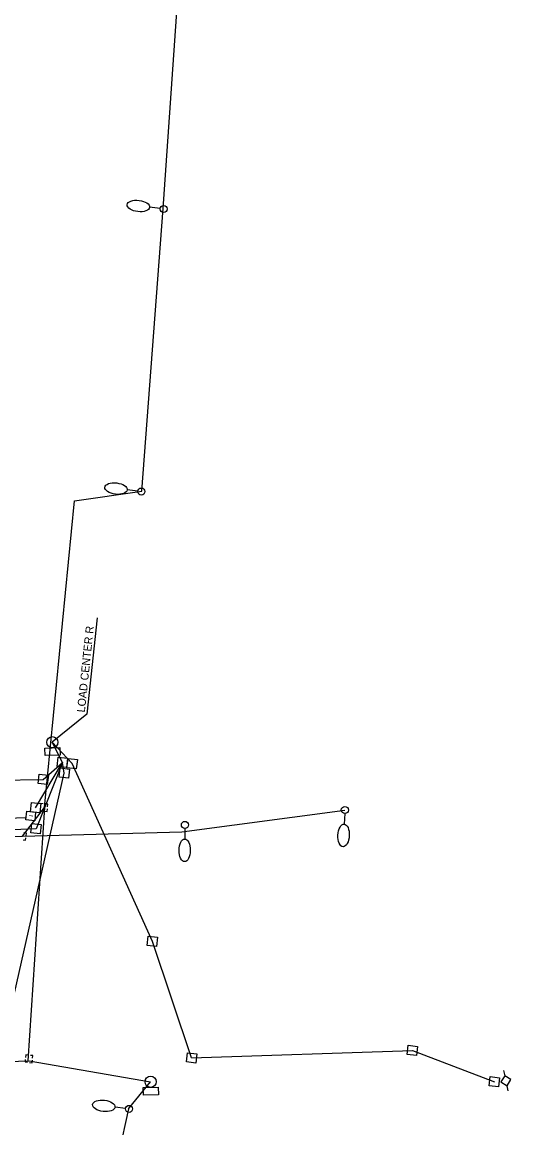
# Model space of a CAD drawing. Extents: x 925407 to 931638, y 609358 to 637063.
# Drawn here: x 931296 to 931638, y 623954 to 624728 of the extents above; entities that cross this region are included whole.
import ezdxf

# ---------------------------------------------------------------- set-up
doc = ezdxf.new("R2010")
doc.units = 0
for name, color, linetype in [('ActivePointCell_dp', 7, 'Continuous'), ('Conduit', 7, 'Continuous'), ('ConduitDB', 7, 'Continuous'), ('ConduitJB', 7, 'Continuous'), ('ConduitOT', 7, 'Continuous'), ('JunctBoxA', 7, 'Continuous'), ('LoadCenter', 7, 'Continuous'), ('LoadCenter_ep', 7, 'Continuous'), ('PoleElec_ep', 7, 'Continuous'), ('PoleLight_ep', 7, 'Continuous'), ('PullBox', 7, 'Continuous')]:
    doc.layers.add(name, color=color, linetype=linetype)

msp = doc.modelspace()

# ---------------------------------------------------------------- linework, layer by layer
at = {"layer": 'ActivePointCell_dp'}
msp.add_line((931348.41, 624311.11), (931341.28, 624243.75), dxfattribs=at)
msp.add_lwpolyline([(931341.28, 624243.75), (931317.05, 624224.02)], dxfattribs=at)
at = {"layer": 'Conduit'}
for p, q in [((931394.8, 624597.39), (931408.64, 624798.05)), ((931379.81, 624399.73), (931394.8, 624597.39)), ((931332.63, 624392.87), (931379.81, 624399.73)), ((931311.62, 624178.47), (931332.63, 624392.87)), ((931296.2, 624158.38), (931311.62, 624178.47)), ((931311.62, 624178.47), (931299.96, 624001.18)), ((931407.77, 624161.41), (931521.93, 624176.6)), ((931086.47, 624152.15), (931296.2, 624158.38)), ((931296.2, 624158.38), (931407.77, 624161.41)), ((931072.34, 623993.5), (931300.82, 624001.21)), ((931300.82, 624001.21), (931385.89, 623986.44)), ((931370.44, 623967.53), (931385.89, 623986.44)), ((931370.44, 623967.53), (931332.04, 623792.24))]:
    msp.add_line(p, q, dxfattribs=at)
at = {"layer": 'ConduitDB'}
for p, q in [((931387.16, 624084.63), (931330.96, 624209.08)), ((931273.51, 623973.41), (931325.4, 624202.39)), ((931213.98, 624196.64), (931310.65, 624198.05)), ((931305.67, 624163.54), (931211.01, 624159.49)), ((931414.61, 624003.2), (931387.16, 624084.63))]:
    msp.add_line(p, q, dxfattribs=at)
msp.add_lwpolyline([(931414.61, 624003.2), (931569.19, 624008.35), (931626.67, 623986.44)], dxfattribs=at)
at = {"layer": 'ConduitJB'}
msp.add_line((931108.8, 624163.39), (931298.74, 624171.44), dxfattribs=at)
at = {"layer": 'ConduitOT'}
for p, q in [((931324.15, 624209.94), (931317.05, 624224.02)), ((931330.96, 624209.08), (931317.05, 624224.02)), ((931305.34, 624178.21), (931324.15, 624209.94)), ((931324.15, 624209.94), (931305.67, 624163.54)), ((931310.65, 624198.05), (931324.15, 624209.94)), ((931325.4, 624202.39), (931324.15, 624209.94))]:
    msp.add_line(p, q, dxfattribs=at)
at = {"layer": 'LoadCenter'}
for p, q in [((931311.93, 624219.97), (931322.38, 624220.24)), ((931312.06, 624214.74), (931311.93, 624219.97)), ((931322.38, 624220.24), (931322.52, 624215.01)), ((931322.52, 624215.01), (931312.06, 624214.74))]:
    msp.add_line(p, q, dxfattribs=at)
msp.add_circle((931317.05, 624224.02), 3.92, dxfattribs=at)
at = {"layer": 'LoadCenter_ep'}
for p, q in [((931380.76, 623982.39), (931391.21, 623982.66)), ((931380.89, 623977.16), (931380.76, 623982.39)), ((931391.35, 623977.43), (931380.89, 623977.16)), ((931391.21, 623982.66), (931391.35, 623977.43))]:
    msp.add_line(p, q, dxfattribs=at)
msp.add_circle((931385.89, 623986.44), 3.92, dxfattribs=at)
at = {"layer": 'PoleElec_ep'}
for p, q in [((931633, 623994.27), (931633.85, 623990.73)), ((931636.41, 623980.17), (931635.56, 623983.71))]:
    msp.add_line(p, q, dxfattribs=at)
msp.add_lwpolyline([(931633.85, 623990.73), (931631.19, 623986.37), (931635.56, 623983.71), (931638.22, 623988.07), (931633.85, 623990.73)], dxfattribs=at)
at = {"layer": 'PoleLight_ep'}
for p, q in [((931392.6, 624597.4), (931385.23, 624598.27)), ((931376.92, 624399.69), (931369.55, 624400.56)), ((931521.81, 624174.13), (931521.45, 624166.71)), ((931409.89, 624163.72), (931409.82, 624156.3)), ((931368.36, 623967.79), (931360.99, 623968.66))]:
    msp.add_line(p, q, dxfattribs=at)
for centre in [(931395.06, 624597.11), (931379.38, 624399.4), (931521.93, 624176.6), (931409.92, 624166.2), (931370.82, 623967.5)]:
    msp.add_circle(centre, 2.47, dxfattribs=at)
for centre, major_axis in [((931377.36, 624599.19), (-7.87, 0.93)), ((931361.68, 624401.49), (-7.87, 0.93)), ((931521.07, 624158.8), (-0.38, -7.91)), ((931409.74, 624148.38), (-0.08, -7.92)), ((931353.13, 623969.59), (-7.87, 0.93))]:
    msp.add_ellipse(centre, major_axis=major_axis, ratio=0.5, dxfattribs=at)
at = {"layer": 'PullBox'}
for p, q in [((931320.53, 624207.05), (931321.26, 624213.55)), ((931321.26, 624213.55), (931327.77, 624212.83)), ((931327.77, 624212.83), (931327.04, 624206.32)), ((931327.34, 624206.18), (931328.07, 624212.69)), ((931328.07, 624212.69), (931334.58, 624211.97)), ((931334.58, 624211.97), (931333.85, 624205.46)), ((931307.04, 624195.16), (931307.76, 624201.67)), ((931307.76, 624201.67), (931314.27, 624200.94)), ((931327.04, 624206.32), (931320.53, 624207.05)), ((931321.78, 624199.5), (931322.51, 624206.01)), ((931322.51, 624206.01), (931329.02, 624205.28)), ((931333.85, 624205.46), (931327.34, 624206.18)), ((931329.02, 624205.28), (931328.29, 624198.77)), ((931313.55, 624194.43), (931307.04, 624195.16)), ((931314.27, 624200.94), (931313.55, 624194.43)), ((931328.29, 624198.77), (931321.78, 624199.5)), ((931301.72, 624175.32), (931302.45, 624181.82)), ((931302.45, 624181.82), (931308.96, 624181.1)), ((931308.96, 624181.1), (931308.23, 624174.59)), ((931298.55, 624169.67), (931299.2, 624175.83)), ((931299.2, 624175.83), (931305.36, 624175.18)), ((931308.23, 624174.59), (931301.72, 624175.32)), ((931305.36, 624175.18), (931304.71, 624169.02)), ((931304.71, 624169.02), (931298.55, 624169.67)), ((931302.05, 624160.65), (931302.78, 624167.16)), ((931302.78, 624167.16), (931309.29, 624166.43)), ((931309.29, 624166.43), (931308.56, 624159.92)), ((931308.56, 624159.92), (931302.05, 624160.65)), ((931383.54, 624081.74), (931384.26, 624088.24)), ((931384.26, 624088.24), (931390.77, 624087.52)), ((931390.77, 624087.52), (931390.05, 624081.01)), ((931390.05, 624081.01), (931383.54, 624081.74)), ((931565.58, 624005.46), (931566.3, 624011.97)), ((931566.3, 624011.97), (931572.81, 624011.24)), ((931572.81, 624011.24), (931572.08, 624004.73)), ((931411, 624000.31), (931411.72, 624006.82)), ((931417.51, 623999.58), (931411, 624000.31)), ((931411.72, 624006.82), (931418.23, 624006.09)), ((931418.23, 624006.09), (931417.51, 623999.58)), ((931572.08, 624004.73), (931565.58, 624005.46)), ((931623.05, 623983.55), (931623.77, 623990.06)), ((931623.77, 623990.06), (931630.28, 623989.33)), ((931630.28, 623989.33), (931629.56, 623982.82)), ((931629.56, 623982.82), (931623.05, 623983.55))]:
    msp.add_line(p, q, dxfattribs=at)
for points in [[(931310.67, 624180.98), (931309, 624181.17), (931308.81, 624179.42)], [(931313.78, 624178.86), (931313.97, 624180.61), (931312.21, 624180.81)], [(931308.64, 624177.92), (931308.45, 624176.2), (931310.11, 624176.02)], [(931311.66, 624175.84), (931313.42, 624175.65)], [(931313.42, 624175.65), (931313.61, 624177.37)], [(931296.58, 624155.62), (931298.34, 624155.43)], [(931298.7, 624158.64), (931298.9, 624160.39), (931297.13, 624160.59)], [(931298.34, 624155.43), (931298.53, 624157.15)], [(931298.15, 624002.04), (931297.96, 624000.32), (931299.63, 624000.14)], [(931300.18, 624005.1), (931298.51, 624005.29), (931298.32, 624003.54)], [(931303.29, 624002.98), (931303.48, 624004.73), (931301.72, 624004.93)], [(931302.93, 623999.77), (931303.12, 624001.49)], [(931301.17, 623999.96), (931302.93, 623999.77)]]:
    msp.add_lwpolyline(points, dxfattribs=at)

# ---------------------------------------------------------------- texts
at = {"layer": 'ActivePointCell_dp'}
msp.add_text('LOAD CENTER R', height=5.6, rotation=83.95697, dxfattribs=at).set_placement((931339.8, 624244.69))
at = {"layer": 'JunctBoxA'}
msp.add_text('J', height=2.48, rotation=83.95697, dxfattribs=at).set_placement((931303.1, 624171.46))

doc.saveas('drawing.dxf')
